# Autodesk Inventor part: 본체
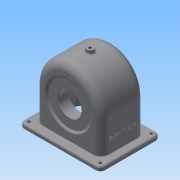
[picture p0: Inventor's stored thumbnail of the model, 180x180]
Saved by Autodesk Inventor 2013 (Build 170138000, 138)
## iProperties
Created: 2016-01
Part Number: 본체
Material: 일반
Document SubType Name: Modeling
Designer: Administrator
Density: 1 g/cm^3
Author: Administrator
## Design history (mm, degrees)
sketch "스케치1"
  geometry: L1 (0, 52)-(62, 52); L2 (0, 52)-(-62, 52); L3 (-70, 44)-(-70, -44); L4 (-62, -52)-(62, -52); L5 (70, -44)-(70, 44); C1 r 2.5 at (-62, 44); C2 r 2.5 at (-62, -44); C3 r 2.5 at (62, 44); C4 r 2.5 at (62, -44); A1 r 8 centre (-62, 44) between (-62, 52) and (-70, 44); A2 r 8 centre (62, 44) between (70, 44) and (62, 52); A3 r 8 centre (62, -44) between (62, -52) and (70, -44); A4 r 8 centre (-62, -44) between (-70, -44) and (-62, -52); 1 further point
  constraints: 10 end point, 8 centre point, 8 point on circle, 2 perpendicular, 2 tangent, 1 collinear
extrude "돌출1" new body sketch "스케치1" distance "d11" = 7; taper "d12" = 0 deg
sketch "스케치2"
  geometry: L1 (0, 0)-(0, 60); L2 (0, 0)-(51, 0); L3 (51, 0)-(57, 0); L4 (57, 0)-(57, 64); L5 (0, 0)-(-51, 0); L6 (-51, 0)-(-57, 0); L7 (-57, 0)-(-57, 64); A1 r 57 centre (0, 64) between (57, 64) and (-57, 64)
  constraints: 14 end point, 3 perpendicular, 2 point on circle, 1 centre point, 1 collinear, 1 point on line, 1 vertical
extrude "돌출2" join sketch "스케치2" stored distance "d24" = 77; taper "d25" = 0 deg
sketch "스케치3"
  geometry: L1 (57, 64)-(57, 7) reference; L2 (-57, 7)-(-57, 64) reference; L3 (-51, 7)-(-51, 64); L4 (51, 64)-(51, 7); L5 (-51, 7)-(-51, 0); L6 (51, 7)-(51, 0); L7 (-62, 0)-(62, 0) reference; L8 (-51, 0)-(51, 0); A1 r 57 centre (0, 64) between (57, 64) and (-57, 64) reference; A2 r 51 centre (0, 64) between (51, 64) and (-51, 64); 1 further point
  constraints: 10 end point, 2 parallel, 2 point on circle, 2 point on line, 1 centre point, 2 other
  dimensions: "d26" = 6 radial gap between concentric circles of A1 A2
extrude "돌출3" cut sketch "스케치3" stored distance "d27" = 67; taper "d28" = 0 deg
node "작업 평면1"
sketch "스케치4"
  geometry: C1 r 6 at (0, 0); 1 further point
  constraints: 1 centre point, 1 coincident
  dimensions: "d30" = 12 diameter of C1
extrude "돌출4" join sketch "스케치4" stored distance "d31" = 67; taper "d32" = 0 deg
sketch "스케치6"
  geometry: C1 r 31 at (0, -60); 1 further point
  constraints: 1 centre point
  dimensions: "d41" = 62 diameter of C1
extrude "돌출5" join sketch "스케치6" distance "d42" = 10; taper "d43" = 0 deg
sketch "스케치7"
  geometry: C1 r 31 at (0, 0) reference; C2 r 20 at (0, 0); 1 further point
  constraints: 1 centre point, 1 coincident
  dimensions: "d44" = 40 diameter of C2
extrude "돌출6" cut sketch "스케치7" distance "d45" = 20; taper "d46" = 0 deg
sketch "스케치9"
  geometry: L1 (-38.5, 60)-(-35.5, 60); L2 (-33.5, 101.426)-(-17.5, 88) reference; L3 (-33.5, 115)-(-33.5, 64) reference; L4 (-17.5, 32)-(-17.5, 88) reference; L5 (-36.714, 97.595)-(-38.5, 99.094); L6 (-35.5, 60)-(-35.5, 96.577); L7 (-38.5, 60)-(-38.5, 99.094); L8 (-36.714, 97.595)-(-35.5, 96.577); L9 (-35.5, 60)-(-9, 60); 1 further point
  constraints: 12 end point, 2 parallel, 1 collinear, 1 perpendicular
revolve "회전2" sketch "스케치9" stored, may be unused: angle "d61" = 90 deg
sketch "스케치10"
  geometry: C1 r 36.577 at (0, 0) reference; C2 r 20 at (0, 0); 1 further point
  constraints: 1 centre point, 1 coincident
  dimensions: "d62" = 40 diameter of C2
extrude "돌출7" cut sketch "스케치10" distance "d63" = 20; taper "d64" = 0 deg
sketch "스케치12"
  geometry: L1 (0, 0)-(0, -24); C1 r 31 at (0, 0) reference; 1 further point
  constraints: 2 end point, 1 coincident, 1 vertical alignment, 2 other
hole "구멍3" sketch "스케치12" at (0, -24) diameter "d77" = 2.459; stored, may be unused: countersink angle "d81" = 90 deg, drill point angle "d83" = 118 deg; dims "d78" = 6, "d79" = 4, "d80" = 2, "d82" = 8
fillet "모깎기1" dims "d87" = 14, "d88" = 9, "d89" = 3
fillet "모깎기2" dims "d90" = 3, "d98" = 1
chamfer "모따기1" distance "d91" = 1; stored, may be unused: second distance "d92" = 2, angle "d93" = 45 deg
sketch "스케치13"
  geometry: 2 further points
  constraints: 1 other
feature "엠보싱1" sketch "스케치13" dims "d96" = 0.5, "d97" = 0
sketch "스케치14"
  geometry: C1 r 6 at (0, 0) reference
hole "구멍4" sketch "스케치14" at (0, 0) diameter "d99" = 4.459; stored, may be unused: countersink angle "d103" = 90 deg, drill point angle "d105" = 118 deg; dims "d100" = 30, "d101" = 4, "d102" = 2, "d104" = 30
sketch "스케치15"
  geometry: L1 (0, 0)-(0, 60); L2 (-33.5, 60)-(-17.5, 60); L3 (-17.5, 60)-(-17.5, 88); L4 (-17.5, 88)-(-33.5, 101.426); L5 (-33.5, 106)-(-33.5, 64) reference; L6 (-33.5, 80)-(-33.5, 40) reference; L7 (-33.5, 60)-(-33.5, 101.426); L8 (-36.572, 97.476)-(-37.428, 98.195) reference; L9 (-34.249, 100.244)-(-35.105, 100.963)
  constraints: 12 end point, 1 midpoint, 1 parallel, 1 perpendicular, 1 point on line, 1 vertical
  dimensions: "d106" = 60 distance of L1.start L1.end; "d111" = 28 distance of L2.end L3.end; "d113" = 5 distance between parallel lines of L4 L8
revolve "회전3" sketch "스케치15" stored, may be unused: angle "d114" = 90 deg
sketch "스케치16"
  geometry: C1 r 20 at (0, 0) reference; C2 r 20 at (0, 0); 1 further point
  constraints: 1 centre point, 1 coincident, 1 concentric
extrude "돌출8" cut sketch "스케치16" distance "d115" = 20; taper "d116" = 0 deg
fillet "모깎기3" dims "d117" = 3
sketch "스케치17" dims "d118" = 56
  geometry: L1 (0, 0)-(0, 28); C1 r 21 at (0, 0) reference; 1 further point
  constraints: 2 end point, 1 coincident, 1 vertical, 1 vertical alignment, 2 other
hole "구멍5" sketch "스케치17" at (0, 28) diameter "d119" = 2.459; stored, may be unused: countersink angle "d123" = 90 deg, drill point angle "d125" = 118 deg; dims "d120" = 7, "d121" = 4, "d122" = 2, "d124" = 9
node "솔리드1"
pattern_circular "원형 패턴2" dims angle "d85" = 360 deg
pattern_circular "원형 패턴3" dims angle "d127" = 360 deg
other parameters: "d29" = 127
